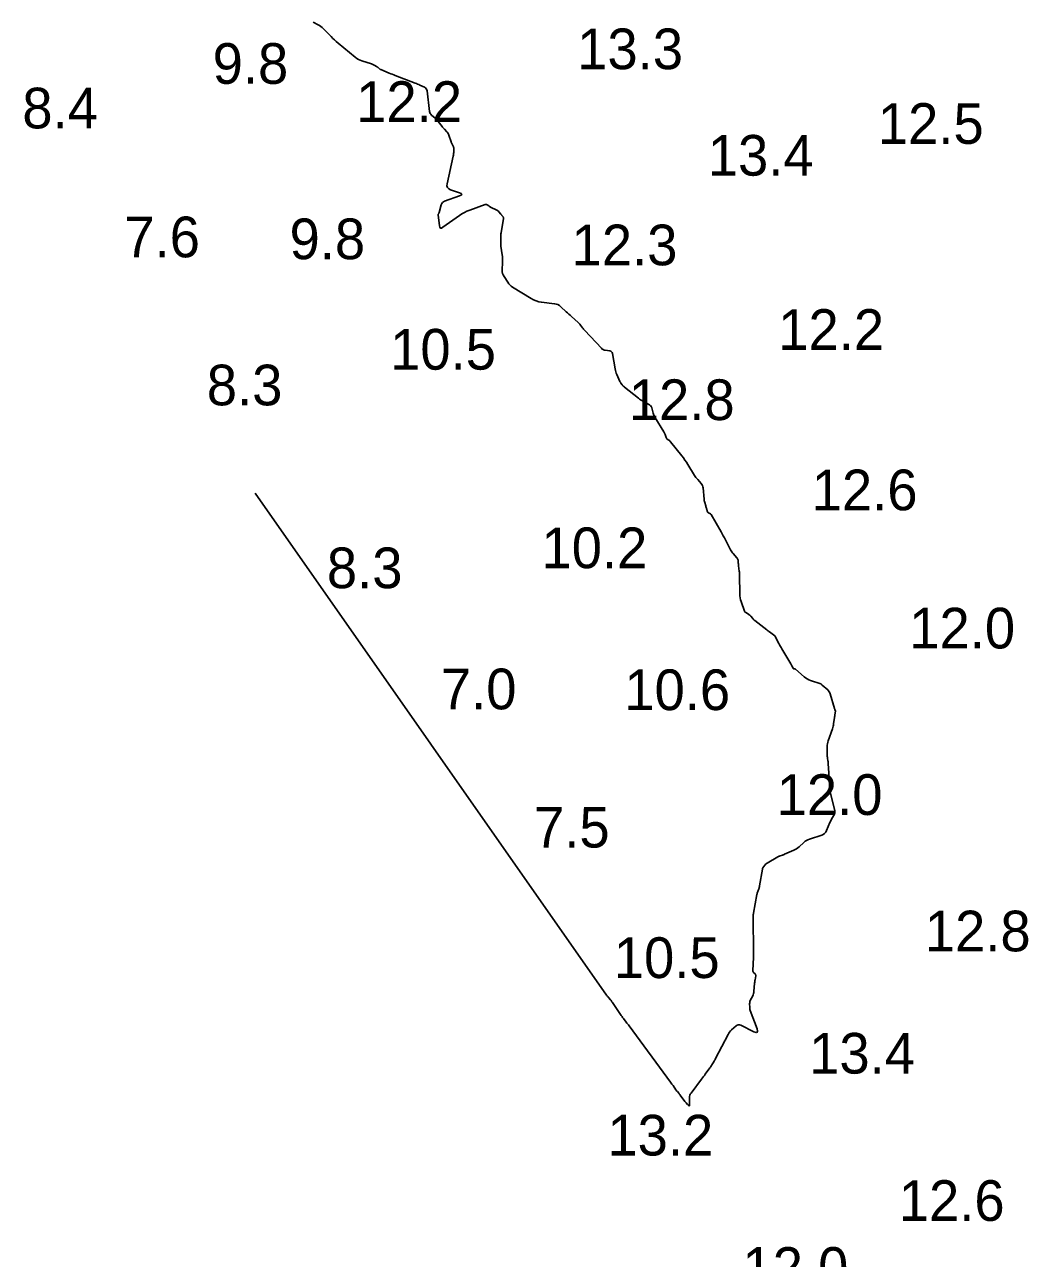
# Model space of a CAD drawing. Extents: x 815352 to 820877, y 582403 to 597439.
# Drawn here: x 817254.7 to 817378, y 596087.5 to 596239.2 of the extents above; entities that cross this region are included whole.
import ezdxf

# ---------------------------------------------------------------- set-up
doc = ezdxf.new("R2010")
doc.units = 0
doc.layers.add('V-CONT-EL12', color=7, linetype='Continuous')
doc.layers.add('V-TOPO-SOUN', color=7, linetype='Continuous')

msp = doc.modelspace()

# ---------------------------------------------------------------- linework, layer by layer
at = {"layer": 'V-CONT-EL12'}
msp.add_lwpolyline([(817283.03, 596181.61), (817326.21, 596119.89), (817326.26, 596119.81), (817326.32, 596119.73), (817326.38, 596119.66), (817326.44, 596119.59), (817326.69, 596119.3), (817326.75, 596119.22), (817326.81, 596119.15), (817326.87, 596119.07), (817326.92, 596119), (817327.93, 596117.49), (817328.01, 596117.37), (817328.1, 596117.25), (817328.18, 596117.14), (817328.27, 596117.02), (817328.62, 596116.57), (817328.7, 596116.46), (817328.79, 596116.34), (817328.88, 596116.23), (817328.96, 596116.11), (817334.08, 596109.17), (817334.16, 596109.07), (817334.23, 596108.96), (817334.3, 596108.86), (817334.38, 596108.76), (817334.73, 596108.25), (817334.77, 596108.2), (817334.81, 596108.14), (817334.85, 596108.09), (817334.9, 596108.03), (817335.07, 596107.82), (817335.11, 596107.76), (817335.15, 596107.71), (817335.2, 596107.65), (817335.24, 596107.6), (817335.83, 596106.79), (817335.86, 596106.75), (817335.9, 596106.71), (817335.93, 596106.67), (817335.97, 596106.64), (817336.15, 596106.46), (817336.17, 596106.44), (817336.19, 596106.42), (817336.22, 596106.39), (817336.24, 596106.37), (817336.34, 596106.29), (817336.36, 596106.27), (817336.37, 596106.27), (817336.38, 596106.28), (817336.38, 596106.31), (817336.38, 596107.25), (817336.39, 596107.41), (817336.43, 596107.57), (817336.49, 596107.71), (817336.58, 596107.85), (817337.88, 596109.56), (817337.99, 596109.71), (817338.11, 596109.87), (817338.23, 596110.02), (817338.34, 596110.18), (817338.9, 596110.94), (817338.96, 596111.03), (817339.03, 596111.13), (817339.09, 596111.22), (817339.15, 596111.31), (817339.38, 596111.7), (817339.43, 596111.79), (817339.49, 596111.89), (817339.54, 596111.99), (817339.59, 596112.09), (817341.13, 596115.04), (817341.22, 596115.2), (817341.32, 596115.35), (817341.44, 596115.49), (817341.56, 596115.61), (817342.11, 596116.11), (817342.25, 596116.2), (817342.39, 596116.25), (817342.54, 596116.25), (817342.71, 596116.19), (817344.31, 596115.39), (817344.57, 596115.29), (817344.73, 596115.32), (817344.77, 596115.47), (817344.7, 596115.74), (817343.86, 596118), (817343.83, 596118.1), (817343.81, 596118.2), (817343.79, 596118.3), (817343.79, 596118.4), (817343.78, 596118.82), (817343.79, 596118.92), (817343.8, 596119.02), (817343.83, 596119.11), (817343.87, 596119.21), (817344.16, 596119.8), (817344.22, 596119.93), (817344.27, 596120.07), (817344.3, 596120.21), (817344.32, 596120.35), (817344.4, 596121.37), (817344.41, 596121.47), (817344.42, 596121.58), (817344.44, 596121.68), (817344.45, 596121.78), (817344.53, 596122.27), (817344.53, 596122.33), (817344.52, 596122.39), (817344.5, 596122.44), (817344.46, 596122.49), (817344.27, 596122.67), (817344.23, 596122.72), (817344.2, 596122.77), (817344.18, 596122.83), (817344.18, 596122.89), (817344.25, 596124.57), (817344.26, 596124.87), (817344.27, 596125.17), (817344.27, 596125.47), (817344.27, 596125.77), (817344.21, 596128.8), (817344.21, 596128.9), (817344.21, 596129), (817344.21, 596129.09), (817344.21, 596129.19), (817344.21, 596129.58), (817344.22, 596129.68), (817344.22, 596129.78), (817344.24, 596129.87), (817344.25, 596129.97), (817344.68, 596132.26), (817344.7, 596132.35), (817344.72, 596132.44), (817344.75, 596132.53), (817344.78, 596132.62), (817344.91, 596132.97), (817344.94, 596133.05), (817344.96, 596133.14), (817344.99, 596133.23), (817345.01, 596133.32), (817345.37, 596135.37), (817345.38, 596135.45), (817345.41, 596135.52), (817345.45, 596135.59), (817345.49, 596135.66), (817345.69, 596135.92), (817345.74, 596135.98), (817345.8, 596136.04), (817345.86, 596136.09), (817345.93, 596136.13), (817347.26, 596136.89), (817347.33, 596136.93), (817347.39, 596136.96), (817347.46, 596136.99), (817347.53, 596137.01), (817347.81, 596137.1), (817347.88, 596137.12), (817347.94, 596137.15), (817348.01, 596137.17), (817348.08, 596137.2), (817349.2, 596137.69), (817349.38, 596137.78), (817349.55, 596137.88), (817349.71, 596137.99), (817349.86, 596138.12), (817350.45, 596138.67), (817350.61, 596138.8), (817350.77, 596138.91), (817350.95, 596139), (817351.13, 596139.08), (817352.64, 596139.56), (817352.83, 596139.65), (817353, 596139.77), (817353.14, 596139.93), (817353.24, 596140.12), (817353.66, 596141.13), (817353.71, 596141.25), (817353.77, 596141.37), (817353.83, 596141.49), (817353.9, 596141.6), (817354.18, 596142.06), (817354.23, 596142.17), (817354.27, 596142.29), (817354.27, 596142.42), (817354.25, 596142.54), (817353.66, 596145.03), (817353.66, 596145.04), (817353.65, 596145.06), (817353.65, 596145.08), (817353.65, 596145.09), (817353.63, 596145.16), (817353.62, 596145.18), (817353.62, 596145.19), (817353.62, 596145.21), (817353.62, 596145.23), (817353.61, 596145.67), (817353.61, 596145.74), (817353.61, 596145.82), (817353.6, 596145.9), (817353.6, 596145.98), (817353.44, 596148.36), (817353.43, 596148.44), (817353.43, 596148.53), (817353.42, 596148.61), (817353.4, 596148.7), (817353.35, 596149.04), (817353.34, 596149.13), (817353.33, 596149.21), (817353.33, 596149.3), (817353.32, 596149.38), (817353.31, 596150.4), (817353.32, 596150.6), (817353.34, 596150.79), (817353.38, 596150.98), (817353.44, 596151.17), (817353.95, 596152.63), (817354, 596152.78), (817354.04, 596152.94), (817354.08, 596153.09), (817354.1, 596153.24), (817354.22, 596154.02), (817354.23, 596154.1), (817354.24, 596154.18), (817354.25, 596154.26), (817354.26, 596154.35), (817354.33, 596154.78), (817354.33, 596154.81), (817354.33, 596154.84), (817354.32, 596154.87), (817354.31, 596154.9), (817354.26, 596155.01), (817354.25, 596155.03), (817354.24, 596155.06), (817354.23, 596155.09), (817354.22, 596155.12), (817353.7, 596156.92), (817353.65, 596157.06), (817353.58, 596157.19), (817353.49, 596157.31), (817353.38, 596157.42), (817352.71, 596157.98), (817352.69, 596158), (817352.67, 596158.01), (817352.66, 596158.03), (817352.65, 596158.04), (817352.59, 596158.11), (817352.58, 596158.12), (817352.56, 596158.14), (817352.54, 596158.15), (817352.53, 596158.16), (817351.26, 596158.59), (817351.05, 596158.67), (817350.85, 596158.78), (817350.66, 596158.9), (817350.48, 596159.04), (817349.42, 596159.96), (817349.4, 596159.98), (817349.38, 596159.99), (817349.35, 596160), (817349.33, 596160.01), (817349.21, 596160.02), (817349.19, 596160.02), (817349.17, 596160.03), (817349.15, 596160.05), (817349.13, 596160.07), (817348.98, 596160.38), (817348.95, 596160.44), (817348.92, 596160.49), (817348.88, 596160.55), (817348.85, 596160.61), (817347.74, 596162.45), (817347.65, 596162.61), (817347.56, 596162.77), (817347.47, 596162.94), (817347.38, 596163.1), (817346.89, 596164.05), (817346.88, 596164.07), (817346.86, 596164.09), (817346.85, 596164.1), (817346.83, 596164.11), (817346.77, 596164.16), (817346.75, 596164.17), (817346.74, 596164.18), (817346.72, 596164.19), (817346.7, 596164.2), (817346.24, 596164.54), (817346.15, 596164.6), (817346.07, 596164.66), (817345.99, 596164.72), (817345.91, 596164.78), (817344.41, 596165.95), (817344.34, 596166), (817344.27, 596166.06), (817344.21, 596166.13), (817344.16, 596166.2), (817343.92, 596166.49), (817343.87, 596166.55), (817343.81, 596166.61), (817343.74, 596166.66), (817343.67, 596166.7), (817343.38, 596166.87), (817343.31, 596166.91), (817343.25, 596166.97), (817343.21, 596167.03), (817343.17, 596167.1), (817342.75, 596168.28), (817342.68, 596168.5), (817342.62, 596168.73), (817342.59, 596168.96), (817342.58, 596169.2), (817342.55, 596171.5), (817342.55, 596171.63), (817342.54, 596171.77), (817342.53, 596171.9), (817342.51, 596172.03), (817342.43, 596172.67), (817342.42, 596172.75), (817342.41, 596172.84), (817342.4, 596172.93), (817342.39, 596173.01), (817342.36, 596173.36), (817342.34, 596173.45), (817342.31, 596173.53), (817342.27, 596173.6), (817342.22, 596173.67), (817341.77, 596174.17), (817341.68, 596174.28), (817341.59, 596174.39), (817341.52, 596174.51), (817341.45, 596174.63), (817340.81, 596175.87), (817340.68, 596176.12), (817340.55, 596176.36), (817340.41, 596176.61), (817340.27, 596176.85), (817339.05, 596178.98), (817339.03, 596179.02), (817338.99, 596179.05), (817338.96, 596179.08), (817338.91, 596179.1), (817338.73, 596179.17), (817338.68, 596179.19), (817338.65, 596179.21), (817338.62, 596179.25), (817338.61, 596179.29), (817338.49, 596179.7), (817338.47, 596179.78), (817338.44, 596179.86), (817338.42, 596179.95), (817338.39, 596180.03), (817338.26, 596180.47), (817338.23, 596180.57), (817338.21, 596180.67), (817338.19, 596180.78), (817338.18, 596180.88), (817338.07, 596182.24), (817338.05, 596182.4), (817338, 596182.54), (817337.93, 596182.67), (817337.83, 596182.8), (817337.4, 596183.27), (817337.29, 596183.39), (817337.19, 596183.52), (817337.1, 596183.65), (817337.01, 596183.78), (817336.18, 596185.14), (817336.01, 596185.41), (817335.83, 596185.67), (817335.64, 596185.93), (817335.45, 596186.18), (817334.06, 596187.92), (817334.02, 596187.97), (817333.97, 596188.02), (817333.92, 596188.06), (817333.87, 596188.1), (817333.66, 596188.26), (817333.61, 596188.3), (817333.57, 596188.35), (817333.53, 596188.4), (817333.51, 596188.46), (817333.39, 596188.82), (817333.36, 596188.9), (817333.32, 596188.98), (817333.29, 596189.06), (817333.24, 596189.13), (817332.14, 596190.95), (817332.08, 596191.06), (817332.03, 596191.18), (817331.98, 596191.3), (817331.95, 596191.42), (817331.77, 596192.09), (817331.76, 596192.13), (817331.74, 596192.17), (817331.72, 596192.2), (817331.7, 596192.24), (817331.59, 596192.36), (817331.56, 596192.4), (817331.53, 596192.42), (817331.5, 596192.45), (817331.47, 596192.47), (817330.66, 596192.9), (817330.52, 596192.98), (817330.38, 596193.07), (817330.24, 596193.17), (817330.11, 596193.27), (817328.41, 596194.64), (817328.39, 596194.66), (817328.36, 596194.68), (817328.34, 596194.71), (817328.31, 596194.73), (817328.22, 596194.81), (817328.19, 596194.84), (817328.17, 596194.86), (817328.15, 596194.88), (817328.13, 596194.91), (817327.97, 596195.14), (817327.93, 596195.19), (817327.9, 596195.24), (817327.88, 596195.29), (817327.85, 596195.34), (817327.47, 596196.2), (817327.4, 596196.36), (817327.34, 596196.53), (817327.3, 596196.69), (817327.26, 596196.87), (817326.92, 596198.76), (817326.88, 596198.89), (817326.82, 596198.98), (817326.72, 596199.05), (817326.59, 596199.09), (817326.03, 596199.17), (817325.9, 596199.2), (817325.77, 596199.25), (817325.66, 596199.32), (817325.56, 596199.42), (817323.52, 596201.6), (817323.45, 596201.68), (817323.38, 596201.76), (817323.31, 596201.84), (817323.25, 596201.93), (817322.99, 596202.27), (817322.93, 596202.36), (817322.86, 596202.44), (817322.79, 596202.51), (817322.71, 596202.59), (817321.89, 596203.32), (817321.72, 596203.47), (817321.56, 596203.61), (817321.4, 596203.76), (817321.24, 596203.91), (817320.58, 596204.53), (817320.41, 596204.67), (817320.22, 596204.78), (817320.02, 596204.85), (817319.81, 596204.89), (817318.2, 596205.08), (817317.87, 596205.14), (817317.54, 596205.23), (817317.23, 596205.36), (817316.94, 596205.52), (817314.65, 596206.94), (817314.48, 596207.06), (817314.32, 596207.2), (817314.18, 596207.35), (817314.06, 596207.53), (817313.6, 596208.24), (817313.5, 596208.43), (817313.43, 596208.62), (817313.39, 596208.82), (817313.39, 596209.03), (817313.43, 596210), (817313.43, 596210.23), (817313.43, 596210.45), (817313.41, 596210.68), (817313.38, 596210.9), (817313.22, 596211.98), (817313.21, 596212.12), (817313.19, 596212.25), (817313.19, 596212.39), (817313.19, 596212.52), (817313.2, 596213.07), (817313.2, 596213.21), (817313.21, 596213.34), (817313.22, 596213.48), (817313.24, 596213.61), (817313.52, 596215.38), (817313.52, 596215.43), (817313.52, 596215.48), (817313.5, 596215.52), (817313.48, 596215.57), (817313.35, 596215.74), (817313.32, 596215.78), (817313.29, 596215.82), (817313.26, 596215.86), (817313.22, 596215.9), (817312.97, 596216.21), (817312.91, 596216.27), (817312.85, 596216.32), (817312.78, 596216.37), (817312.71, 596216.41), (817311.94, 596216.78), (817311.89, 596216.81), (817311.83, 596216.84), (817311.78, 596216.88), (817311.73, 596216.91), (817311.52, 596217.06), (817311.47, 596217.09), (817311.41, 596217.11), (817311.35, 596217.11), (817311.29, 596217.09), (817309.39, 596216.41), (817309.05, 596216.28), (817308.73, 596216.12), (817308.42, 596215.95), (817308.13, 596215.75), (817306.09, 596214.29), (817305.92, 596214.2), (817305.79, 596214.2), (817305.7, 596214.3), (817305.66, 596214.49), (817305.5, 596215.84), (817305.5, 596215.86), (817305.5, 596215.88), (817305.51, 596215.9), (817305.52, 596215.92), (817305.57, 596216), (817305.58, 596216.02), (817305.59, 596216.04), (817305.6, 596216.06), (817305.61, 596216.09), (817305.88, 596217.05), (817305.94, 596217.2), (817306.03, 596217.33), (817306.15, 596217.43), (817306.3, 596217.5), (817308.13, 596218.15), (817308.33, 596218.25), (817308.4, 596218.35), (817308.33, 596218.44), (817308.13, 596218.53), (817307.03, 596218.9), (817306.8, 596219.01), (817306.65, 596219.18), (817306.59, 596219.39), (817306.61, 596219.64), (817307.37, 596223.05), (817307.39, 596223.16), (817307.4, 596223.27), (817307.41, 596223.37), (817307.42, 596223.48), (817307.43, 596224), (817307.42, 596224.07), (817307.41, 596224.14), (817307.39, 596224.21), (817307.35, 596224.27), (817307.21, 596224.53), (817307.17, 596224.59), (817307.14, 596224.66), (817307.11, 596224.72), (817307.09, 596224.79), (817306.81, 596225.63), (817306.77, 596225.73), (817306.72, 596225.83), (817306.66, 596225.93), (817306.59, 596226.01), (817306.29, 596226.35), (817306.21, 596226.44), (817306.14, 596226.53), (817306.06, 596226.61), (817305.99, 596226.7), (817305.51, 596227.3), (817305.42, 596227.41), (817305.32, 596227.51), (817305.22, 596227.61), (817305.12, 596227.71), (817304.7, 596228.08), (817304.61, 596228.18), (817304.54, 596228.29), (817304.49, 596228.41), (817304.46, 596228.54), (817304.14, 596231.06), (817304.1, 596231.21), (817304.04, 596231.33), (817303.95, 596231.43), (817303.82, 596231.51), (817303.26, 596231.77), (817303.12, 596231.84), (817302.98, 596231.9), (817302.84, 596231.96), (817302.7, 596232.02), (817300.23, 596232.95), (817300.05, 596233.03), (817299.86, 596233.1), (817299.68, 596233.17), (817299.49, 596233.25), (817298.47, 596233.67), (817298.42, 596233.69), (817298.38, 596233.71), (817298.34, 596233.74), (817298.31, 596233.77), (817298.16, 596233.89), (817298.12, 596233.92), (817298.08, 596233.94), (817298.04, 596233.97), (817298, 596234), (817297.63, 596234.24), (817297.55, 596234.28), (817297.47, 596234.32), (817297.39, 596234.36), (817297.3, 596234.39), (817296.13, 596234.75), (817295.91, 596234.83), (817295.7, 596234.93), (817295.51, 596235.05), (817295.32, 596235.19), (817293.2, 596236.94), (817292.98, 596237.13), (817292.76, 596237.32), (817292.55, 596237.52), (817292.34, 596237.73), (817291.37, 596238.74), (817291.24, 596238.87), (817291.09, 596238.98), (817290.94, 596239.08), (817290.78, 596239.17), (817290.13, 596239.51)], dxfattribs=at)

# ---------------------------------------------------------------- texts
at = {"layer": 'V-TOPO-SOUN'}
for s, p in [('13.3 ', (817322.59, 596233.73)), ('9.8', (817277.79, 596231.93)), ('12.2 ', (817295.43, 596227.24)), ('8.4', (817254.4, 596226.45)), ('12.5 ', (817359.54, 596224.55)), ('13.4 ', (817338.64, 596220.64)), ('7.6', (817266.94, 596210.6)), ('9.8', (817287.24, 596210.37)), ('12.3 ', (817321.9, 596209.62)), ('12.2 ', (817347.3, 596199.22)), ('10.5 ', (817299.6, 596196.79)), ('8.3', (817277.07, 596192.4)), ('12.8 ', (817328.93, 596190.59)), ('12.6 ', (817351.41, 596179.5)), ('10.2 ', (817318.2, 596172.38)), ('8.3', (817291.83, 596169.92)), ('12.0 ', (817363.4, 596162.51)), ('7.0', (817305.84, 596155.03)), ('10.6 ', (817328.38, 596154.93)), ('12.0 ', (817347.1, 596142.04)), ('7.5', (817317.29, 596138.03)), ('12.8 ', (817365.31, 596125.27)), ('10.5 ', (817327.09, 596121.99)), ('13.4 ', (817351.1, 596110.24)), ('13.2 ', (817326.3, 596100.17)), ('12.6 ', (817362.11, 596092.13)), ('12.0 ', (817342.9, 596083.9))]:
    msp.add_text(s, height=5, dxfattribs=at).set_placement(p)

doc.saveas('drawing.dxf')
